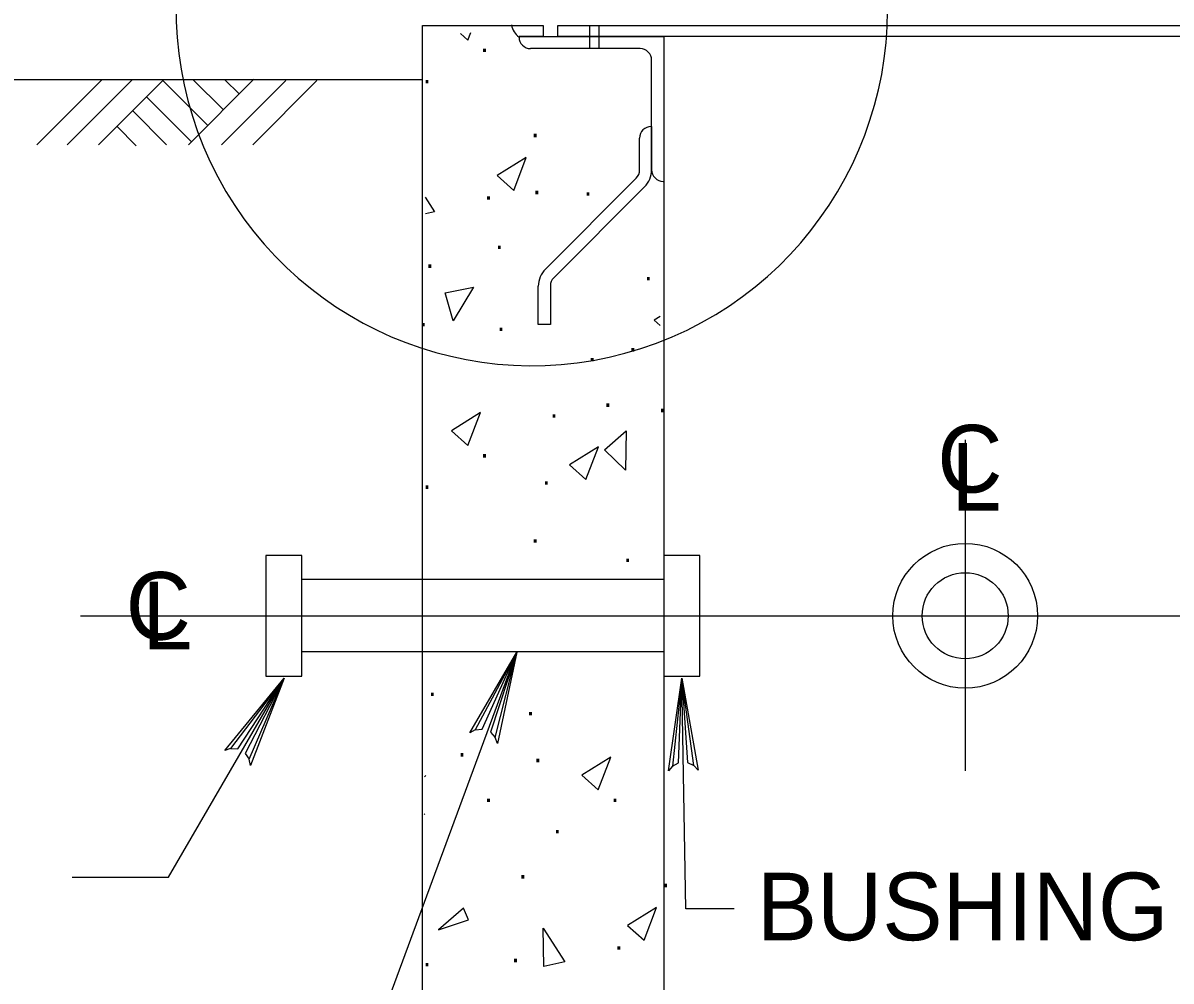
# Model space of a CAD drawing. Extents: x 638447 to 639352, y 298406 to 299000.
# Drawn here: x 638691.3 to 638748.4, y 298869 to 298916.6 of the extents above; entities that cross this region are included whole.
import ezdxf

# ---------------------------------------------------------------- set-up
doc = ezdxf.new("R2010")
doc.units = 0
doc.layers.add('2', color=7, linetype='Continuous')
doc.layers.add('3', color=7, linetype='Continuous')

msp = doc.modelspace()

# ---------------------------------------------------------------- linework, layer by layer
at = {"layer": '2'}
for p, q in [((638719.472375, 298916.49), (638719.472375, 298915.398)), ((638719.940375, 298916.49), (638719.940375, 298915.398)), ((638715.964375, 298915.954), (638723.164375, 298915.954)), ((638723.164375, 298915.954), (638723.164375, 298908.754)), ((638721.988375, 298915.354), (638716.540375, 298915.354)), ((638722.564375, 298909.33), (638722.564375, 298914.778)), ((638711.178375, 298913.796), (638686.084375, 298913.796)), ((638691.980375, 298910.578), (638695.194375, 298913.792)), ((638693.484375, 298910.578), (638696.716375, 298913.81)), ((638695.040375, 298910.578), (638698.270375, 298913.81)), ((638698.202375, 298913.81), (638700.482375, 298911.53)), ((638699.514375, 298910.578), (638702.764375, 298913.828)), ((638699.756375, 298913.81), (638701.242375, 298912.324)), ((638701.156375, 298910.578), (638704.354375, 298913.776)), ((638701.330375, 298913.81), (638702.038375, 298913.102)), ((638702.712375, 298910.578), (638705.908375, 298913.776)), ((638697.424375, 298912.964), (638699.652375, 298910.734)), ((638696.732375, 298912.272), (638698.426375, 298910.578)), ((638695.956375, 298911.494), (638696.922375, 298910.526)), ((638722.564375, 298911.482), (638722.564375, 298909.33)), ((638721.964375, 298909.322), (638721.964375, 298910.906)), ((638717.276375, 298904.394), (638721.796375, 298908.914)), ((638722.212375, 298908.482), (638717.692375, 298903.962)), ((638716.924375, 298901.642), (638716.924375, 298903.546)), ((638717.524375, 298903.556), (638717.524375, 298901.642)), ((638717.524375, 298901.642), (638716.924375, 298901.642)), ((638738.164375, 298895.906), (638738.164375, 298879.436)), ((638711.164375, 298888.954), (638705.164375, 298888.954)), ((638723.164375, 298888.954), (638711.164375, 298888.954)), ((638694.150375, 298887.154), (638774.544375, 298887.154)), ((638738.164375, 298887.154), (638738.164375, 298887.154)), ((638711.164375, 298885.354), (638705.164375, 298885.354)), ((638723.164375, 298885.354), (638711.164375, 298885.354))]:
    msp.add_line(p, q, dxfattribs=at)
for points in [[(638711.164375, 298915.954), (638711.164375, 298916.512), (638717.164375, 298916.512), (638717.164375, 298915.954), (638715.964375, 298915.954)], [(638713.420375, 298915.782), (638713.564375, 298916.158)], [(638715.964375, 298915.954), (638723.164375, 298915.954), (638723.164375, 298867.954), (638711.164375, 298867.954), (638711.164375, 298915.954)], [(638713.048375, 298916.114), (638713.420375, 298915.782)], [(638711.292375, 298907.966), (638711.764375, 298907.238)], [(638711.764375, 298907.238), (638711.306375, 298907.134)], [(638722.990375, 298902.036), (638722.696375, 298901.85)], [(638722.696375, 298901.85), (638722.994375, 298901.582)], [(638701.646375, 298859.724), (638706.390375, 298859.724), (638715.862375, 298885.346)], [(638713.780375, 298881.478), (638714.132375, 298881.516), (638715.862375, 298885.346), (638713.780375, 298881.478), (638713.520375, 298881.338), (638715.862375, 298885.346), (638714.542375, 298881.36), (638714.778375, 298881.104), (638715.862375, 298885.346), (638714.888375, 298880.81), (638714.778375, 298881.104)], [(638693.728375, 298874.15), (638698.528375, 298874.15), (638704.274375, 298884.044)], [(638701.610375, 298880.55), (638701.966375, 298880.532), (638704.274375, 298884.044), (638701.610375, 298880.55), (638701.334375, 298880.452), (638704.274375, 298884.044), (638702.346375, 298880.314), (638702.540375, 298880.024), (638704.274375, 298884.044), (638702.602375, 298879.716), (638702.540375, 298880.024)], [(638723.594375, 298879.676), (638723.906375, 298879.844), (638724.064375, 298884.044), (638723.594375, 298879.676), (638723.406375, 298879.45), (638724.064375, 298884.044), (638724.346375, 298879.856), (638724.660375, 298879.708), (638724.064375, 298884.044), (638724.874375, 298879.476), (638724.660375, 298879.708)], [(638726.668375, 298872.588), (638724.268375, 298872.588), (638724.064375, 298884.044)], [(638711.258375, 298879.154), (638711.326375, 298879.214)], [(638711.278375, 298877.27), (638711.242375, 298877.304)]]:
    msp.add_lwpolyline(points, dxfattribs=at)
for points in [[(638717.902375, 298915.954), (638717.902375, 298916.512), (638758.388375, 298916.512), (638758.388375, 298915.954)], [(638716.324375, 298909.938), (638714.884375, 298909.038), (638715.700375, 298908.306)], [(638712.292375, 298903.218), (638713.696375, 298903.494), (638712.688375, 298901.826)], [(638714.044375, 298897.254), (638712.604375, 298896.354), (638713.420375, 298895.622)], [(638720.224375, 298895.406), (638721.304375, 298896.342), (638721.256375, 298894.398)], [(638719.912375, 298895.562), (638718.472375, 298894.662), (638719.288375, 298893.93)], [(638705.164375, 298884.154), (638705.164375, 298890.154), (638703.364375, 298890.154), (638703.364375, 298884.154)], [(638724.964375, 298884.154), (638724.964375, 298890.154), (638723.164375, 298890.154), (638723.164375, 298884.154)], [(638720.530375, 298880.126), (638719.090375, 298879.226), (638719.906375, 298878.494)], [(638713.450375, 298872.038), (638713.198375, 298872.614), (638711.962375, 298871.546)], [(638722.810375, 298872.65), (638721.370375, 298871.75), (638722.186375, 298871.018)], [(638718.250375, 298869.95), (638717.206375, 298869.71), (638717.170375, 298871.618)]]:
    msp.add_lwpolyline(points, close=True, dxfattribs=at)
for radius in [3.6, 2.141689]:
    msp.add_circle((638738.164421, 298887.154868), radius, dxfattribs=at)
for centre, radius, start, end in [((638716.603191, 298917.290438), 17.699271, 42.9605194, 13.0396806), ((638716.504228, 298916.685683), 0.927976, 189.2581694, 234.4295056), ((638716.540421, 298915.930868), 0.576, 180, 270), ((638721.988421, 298914.778868), 0.576, 0, 90), ((638722.540373, 298910.906372), 0.576, 90, 180), ((638721.388373, 298909.320959), 0.576, 315, 0), ((638721.364373, 298909.330884), 1.2, 315, 0), ((638723.140421, 298909.330868), 0.576, 180, 270), ((638718.124373, 298903.545315), 1.2, 135, 180), ((638718.100373, 298903.555241), 0.576, 135, 180)]:
    msp.add_arc(centre, radius, start, end, dxfattribs=at)

# ---------------------------------------------------------------- texts
for p in [(638714.044375, 298915.182), (638711.176375, 298913.622), (638716.564375, 298910.946), (638716.648375, 298908.114), (638719.192375, 298908.042), (638714.236375, 298907.838), (638714.776375, 298905.39), (638711.320375, 298904.454), (638722.192375, 298903.83), (638710.984375, 298901.538), (638714.860375, 298901.31), (638721.424375, 298900.29), (638719.396375, 298899.798), (638720.176375, 298897.542), (638722.900375, 298897.278), (638717.500375, 298897.002), (638714.044375, 298895.022), (638711.176375, 298893.462), (638717.116375, 298893.666), (638716.564375, 298890.786), (638721.160375, 298889.826), (638711.446375, 298883.162), (638716.330375, 298882.202), (638712.922375, 298880.15), (638716.690375, 298879.874), (638714.242375, 298877.894), (638720.530375, 298877.894), (638717.662375, 298876.334), (638715.946375, 298874.09), (638723.050375, 298873.658), (638720.722375, 298870.55), (638711.182375, 298869.722), (638715.586375, 298869.926)]:
    msp.add_text('.', height=1.116, dxfattribs=at).set_placement(p)
at = {"layer": '3'}
for s, p in [('C', (638736.776375, 298893.284)), ('L', (638737.470375, 298892.388)), ('C', (638696.392375, 298885.968)), ('L', (638697.212375, 298885.486)), ('BUSHING', (638727.798375, 298871.02))]:
    msp.add_text(s, height=3.359988, dxfattribs=at).set_placement(p)

doc.saveas('drawing.dxf')
